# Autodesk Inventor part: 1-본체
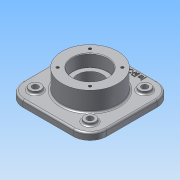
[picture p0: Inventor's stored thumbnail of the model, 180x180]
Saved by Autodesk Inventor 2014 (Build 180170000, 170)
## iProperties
Created: 2015-09
Part Number: 1-본체
Material: 알루미늄 6061
Document SubType Name: Modeling
Designer: study
Mass: 1464.68 g
Surface Area: 800.934 cm^2
Volume: 540.471 cm^3
Density: 2.71 g/cm^3
Appearance: 알루미늄 - 평지
Author: study
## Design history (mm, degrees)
sketch "스케치1"
  geometry: L1 (-75, -75)-(75, -75); L2 (75, -75)-(75, 75); L3 (75, 75)-(-75, 75); L4 (-75, 75)-(-75, -75); L5 (-75, -75)-(75, 75); L6 (75, -75)-(-75, 75); 3 further points
  constraints: 12 end point, 3 midpoint, 2 parallel, 2 perpendicular, 1 coincident, 1 horizontal
  dimensions: "d0" = 150 distance of L2.end L3.end
extrude "돌출1" new body sketch "스케치1" distance "d1" = 12; taper "d2" = 0 deg
node "작업 평면1"
sketch "스케치2"
  geometry: C1 r 50 at (0, 0); 1 further point
  constraints: 1 centre point, 1 coincident
  dimensions: "d4" = 100 diameter of C1
extrude "돌출2" join sketch "스케치2" distance "d5" = 70; taper "d6" = 0 deg
fillet "모깎기1" dims "d7" = 30
sketch "스케치3"
  geometry: C1 r 50 at (0, 0) reference; C2 r 10 at (-49, 49); C3 r 10 at (49, 49); C4 r 10 at (49, -49); C5 r 10 at (-49, -49); 4 further points
  constraints: 4 centre point, 4 coincident, 3 equal radius, 2 horizontal alignment, 2 vertical alignment
  dimensions: "d8" = 98 distance of C3.centre C2.centre; "d9" = 49 horizontal distance of C1.centre C2.centre; "d10" = 98 distance of C5.centre C2.centre; "d11" = 49 horizontal distance of C1.centre C2.centre; "d12" = 20 diameter of C2
extrude "돌출3" join sketch "스케치3" distance "d13" = 5; taper "d14" = 0 deg
sketch "스케치4"
  geometry: C1 r 50 at (0, 0) reference; 4 further points
  constraints: 2 horizontal alignment, 2 vertical alignment
  dimensions: "d15" = 98 distance of point (49, 49) point (-49, 49); "d16" = 49 horizontal distance of C1.centre point (-49, 49); "d17" = 98 distance of point (-49, 49) point (-49, -49); "d18" = 49 horizontal distance of C1.centre point (-49, 49)
hole "구멍1" sketch "스케치4" at (-49, 49), (49, 49), (49, -49), (-49, -49) diameter "d19" = 11; stored, may be unused: countersink angle "d23" = 90 deg, drill point angle "d25" = 118 deg; dims "d20" = 6, "d21" = 4, "d22" = 2, "d24" = 8
hole "구멍2" diameter "d28" = 45; stored, may be unused: countersink angle "d32" = 90 deg, drill point angle "d34" = 118 deg; dims "d26" = 10, "d27" = 10, "d29" = 6, "d30" = 62, "d31" = 22, "d33" = 8
hole "구멍3" diameter "d37" = 45; stored, may be unused: countersink angle "d41" = 90 deg, drill point angle "d43" = 118 deg; dims "d35" = 10, "d36" = 10, "d38" = 6, "d39" = 62, "d40" = 22, "d42" = 8
sketch "스케치5"
  geometry: C1 r 50 at (0, 0) reference; 1 further point
  constraints: 1 vertical alignment, 1 other
  dimensions: "d44" = 65 distance of C1.centre point (0, 65)
feature "엠보싱1" sketch "스케치5" dims "d8" = 98, "d45" = 1, "d46" = 0
fillet "모깎기2" dims "d47" = 3
sketch "스케치6"
  geometry: L1 (-28.991, -28.991)-(28.991, -28.991); L2 (28.991, -28.991)-(28.991, 28.991); L3 (28.991, 28.991)-(-28.991, 28.991); L4 (-28.991, 28.991)-(-28.991, -28.991); L5 (-28.991, -28.991)-(28.991, 28.991); L6 (28.991, -28.991)-(-28.991, 28.991); C1 r 50 at (0, 0) reference; 4 further points
  constraints: 12 end point, 4 coincident, 2 midpoint, 2 parallel, 2 perpendicular, 1 horizontal
  dimensions: "d48" = 82 distance of L1.end L3.end
hole "구멍4" sketch "스케치6" at (-28.991, 28.991), (-28.991, -28.991), (28.991, -28.991), (28.991, 28.991) diameter "d50" = 4.917; stored, may be unused: countersink angle "d54" = 90 deg, drill point angle "d56" = 118 deg; dims "d51" = 10, "d52" = 62, "d53" = 22, "d55" = 13
fillet "모깎기3" dims "d57" = 0.3
chamfer "모따기1" distance "d58" = 1; stored, may be unused: second distance "d59" = 2, angle "d60" = 45 deg
fillet "모깎기4" dims "d61" = 3
sketch "스케치7"
  geometry: C1 r 2.458 at (-28.991, 28.991) reference; C2 r 2.458 at (28.991, 28.991) reference; C3 r 2.458 at (28.991, -28.991) reference; C4 r 2.458 at (-28.991, -28.991) reference; 4 further points
  constraints: 4 coincident
hole "구멍5" sketch "스케치7" at (-28.991, 28.991), (28.991, 28.991), (28.991, -28.991), (-28.991, -28.991) diameter "d62" = 4.917; stored, may be unused: countersink angle "d66" = 90 deg, drill point angle "d68" = 118 deg; dims "d63" = 10, "d64" = 62, "d65" = 22, "d67" = 13
node "솔리드1"
other parameters: "d3" = 23
